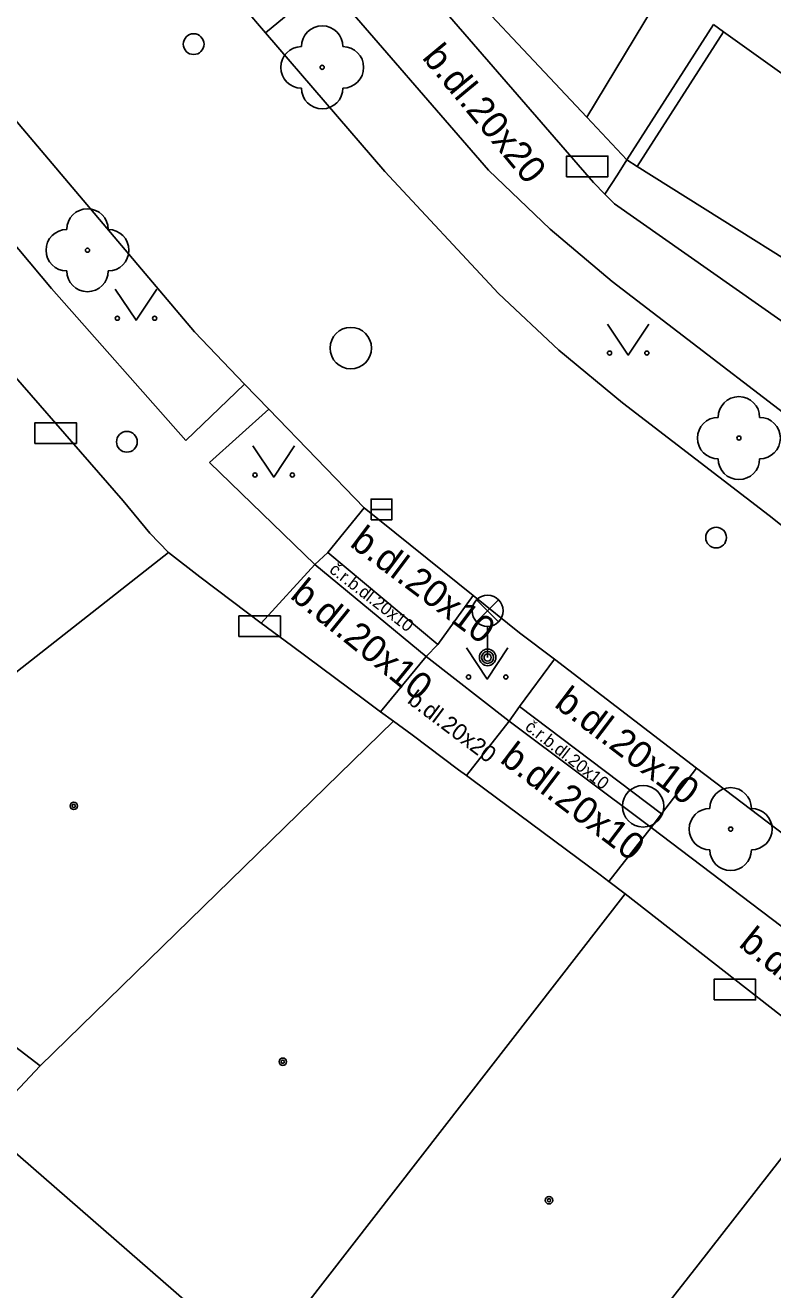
# Model space of a CAD drawing. Extents: x -595546 to -593986, y -1160845 to -1159202.
# Drawn here: x -595188.46 to -595170.44, y -1160627.43 to -1160596.94 of the extents above; entities that cross this region are included whole.
import ezdxf

# ---------------------------------------------------------------- set-up
doc = ezdxf.new("R2010")
doc.units = 0
for name, color, linetype in [('Level 22', 7, 'Continuous'), ('Level 24', 7, 'Continuous'), ('Level 27', 7, 'Continuous'), ('Level 28', 7, 'Continuous'), ('Level 33', 7, 'Continuous'), ('Level 36', 7, 'Continuous'), ('Level 39', 7, 'Continuous'), ('TM - budovy zdene_ betonove - VP', 7, 'Continuous'), ('TM - chodniky - VP', 7, 'Continuous'), ('TM - komunikace - VP', 7, 'Continuous'), ('TM - letecke snimky - pomocna linie', 7, 'Continuous'), ('TM - plot zdeny_ ohradni zed - VP', 7, 'Continuous'), ('TM - popis povrchu', 7, 'Continuous'), ('TM - rozhrani mezi zpev. plochami mezi sebou - VP', 7, 'Continuous'), ('TM - rozhrani ploch obecne - VP', 7, 'Continuous'), ('TM - vstup do budovy - zdene_ betonove', 7, 'Continuous'), ('TM - zed operna - VP', 7, 'Continuous')]:
    doc.layers.add(name, color=color, linetype=linetype)

msp = doc.modelspace()

# ---------------------------------------------------------------- linework, layer by layer
at = {"layer": 'Level 22'}
for centre in [(-595181.3, -1160597.95), (-595186.96, -1160602.36), (-595171.25, -1160606.89), (-595171.45, -1160616.32)]:
    msp.add_circle(centre, 0.05, dxfattribs=at)
for centre, start, end in [((-595181.3, -1160597.45), 0, 180), ((-595181.8, -1160597.95), 90, 270), ((-595180.8, -1160597.95), 270, 90), ((-595181.3, -1160598.45), 180, 0), ((-595186.96, -1160601.86), 0, 180), ((-595187.46, -1160602.36), 90, 270), ((-595186.46, -1160602.36), 270, 90), ((-595186.96, -1160602.86), 180, 0), ((-595171.25, -1160606.39), 0, 180), ((-595171.75, -1160606.89), 90, 270), ((-595170.75, -1160606.89), 270, 90), ((-595171.25, -1160607.39), 180, 0), ((-595171.45, -1160615.82), 0, 180), ((-595171.95, -1160616.32), 90, 270), ((-595170.95, -1160616.32), 270, 90), ((-595171.45, -1160616.82), 180, 0)]:
    msp.add_arc(centre, 0.5, start, end, dxfattribs=at)
at = {"layer": 'Level 24'}
for points in [[(-595175.408, -1160600.589), (-595174.408, -1160600.589), (-595174.408, -1160600.089), (-595175.408, -1160600.089)], [(-595188.228, -1160607.019), (-595187.228, -1160607.019), (-595187.228, -1160606.519), (-595188.228, -1160606.519)], [(-595183.308, -1160611.679), (-595182.308, -1160611.679), (-595182.308, -1160611.179), (-595183.308, -1160611.179)], [(-595171.848, -1160620.439), (-595170.848, -1160620.439), (-595170.848, -1160619.939), (-595171.848, -1160619.939)]]:
    msp.add_lwpolyline(points, close=True, dxfattribs=at)
at = {"layer": 'Level 27'}
msp.add_line((-595180.12, -1160608.61), (-595179.62, -1160608.61), dxfattribs=at)
msp.add_lwpolyline([(-595180.12, -1160608.86), (-595179.62, -1160608.86), (-595179.62, -1160608.36), (-595180.12, -1160608.36)], close=True, dxfattribs=at)
for centre in [(-595180.61, -1160604.72), (-595173.56, -1160615.77)]:
    msp.add_circle(centre, 0.5, dxfattribs=at)
at = {"layer": 'Level 28'}
for centre in [(-595184.4, -1160597.39), (-595186.01, -1160606.98), (-595171.8, -1160609.29)]:
    msp.add_circle(centre, 0.25, dxfattribs=at)
at = {"layer": 'Level 33'}
for p, q in [((-595177.575, -1160611.32), (-595177.045, -1160610.79)), ((-595177.575, -1160610.79), (-595177.045, -1160611.32)), ((-595177.31, -1160611.43), (-595177.31, -1160612.18))]:
    msp.add_line(p, q, dxfattribs=at)
for centre, radius in [((-595177.31, -1160611.055), 0.375), ((-595177.31, -1160612.18), 0.2), ((-595177.31, -1160612.18), 0.145), ((-595177.31, -1160612.18), 0.0876)]:
    msp.add_circle(centre, radius, dxfattribs=at)
at = {"layer": 'Level 36'}
for points in [[(-595186.29, -1160603.3), (-595185.79, -1160604.05), (-595185.29, -1160603.3)], [(-595174.42, -1160604.14), (-595173.92, -1160604.89), (-595173.42, -1160604.14)], [(-595182.97, -1160607.08), (-595182.47, -1160607.83), (-595181.97, -1160607.08)], [(-595177.82, -1160611.95), (-595177.32, -1160612.7), (-595176.82, -1160611.95)]]:
    msp.add_lwpolyline(points, dxfattribs=at)
for centre in [(-595186.24, -1160604), (-595185.341, -1160604), (-595174.37, -1160604.84), (-595173.471, -1160604.84), (-595182.92, -1160607.78), (-595182.021, -1160607.78), (-595177.77, -1160612.65), (-595176.871, -1160612.65)]:
    msp.add_circle(centre, 0.05, dxfattribs=at)
at = {"layer": 'Level 39'}
for centre, radius in [((-595187.29, -1160615.76), 0.09), ((-595187.29, -1160615.76), 0.0398), ((-595182.25, -1160621.93), 0.09), ((-595182.25, -1160621.93), 0.0398), ((-595175.83, -1160625.27), 0.09), ((-595175.83, -1160625.27), 0.0398)]:
    msp.add_circle(centre, radius, dxfattribs=at)
at = {"layer": 'TM - budovy zdene_ betonove - VP'}
for points in [[(-595171.62, -1160597.09), (-595171.86, -1160596.92)], [(-595167.48, -1160600.05), (-595171.62, -1160597.09)], [(-595189.73, -1160604.24), (-595186.1, -1160608.4)], [(-595185.46, -1160609.18), (-595185.01, -1160609.65)], [(-595185.01, -1160609.65), (-595194.52, -1160617.12)], [(-595185.01, -1160609.65), (-595184.25, -1160610.24)], [(-595183.46, -1160610.83), (-595182.77, -1160611.35)], [(-595182.77, -1160611.35), (-595182.04, -1160611.89)], [(-595180.28, -1160613.2), (-595179.89, -1160613.49)], [(-595179.58, -1160613.72), (-595188.1, -1160622.03)], [(-595179.89, -1160613.49), (-595179.58, -1160613.72)], [(-595179.58, -1160613.72), (-595179.13, -1160614.05)], [(-595178.01, -1160614.89), (-595177.82, -1160615.03)], [(-595177.82, -1160615.03), (-595177.66, -1160615.15)], [(-595188.1, -1160622.03), (-595194.52, -1160617.12)], [(-595174.6, -1160617.42), (-595174.39, -1160617.58)], [(-595174.39, -1160617.58), (-595173.99, -1160617.88)], [(-595182.82, -1160629.25), (-595173.99, -1160617.88)], [(-595173.99, -1160617.88), (-595169.99, -1160621.01)], [(-595188.1, -1160622.03), (-595189.46, -1160623.47)], [(-595172.23, -1160626.83), (-595168.55, -1160622.11)], [(-595182.82, -1160629.25), (-595189.46, -1160623.47)], [(-595172.23, -1160626.83), (-595177.6, -1160633.68)]]:
    msp.add_lwpolyline(points, dxfattribs=at)
at = {"layer": 'TM - chodniky - VP'}
for points in [[(-595182.67, -1160597.12), (-595181.2, -1160595.9)], [(-595181.2, -1160595.9), (-595177.29, -1160600.43)], [(-595187.83, -1160603.28), (-595192.39, -1160597.84)], [(-595177.29, -1160600.43), (-595175.8, -1160601.85)], [(-595175.8, -1160601.85), (-595174.31, -1160603.11)], [(-595174.31, -1160603.11), (-595168.35, -1160607.68)], [(-595184.59, -1160606.95), (-595187.83, -1160603.28)], [(-595183.17, -1160605.59), (-595184.59, -1160606.95)], [(-595184.02, -1160607.48), (-595182.59, -1160606.19)], [(-595181.48, -1160609.94), (-595184.02, -1160607.48)], [(-595180.29, -1160608.57), (-595181.16, -1160609.65)], [(-595181.16, -1160609.65), (-595181.48, -1160609.94)], [(-595178.51, -1160611.87), (-595177.66, -1160610.69)], [(-595178.79, -1160612.16), (-595178.51, -1160611.87)], [(-595176.79, -1160613.72), (-595178.79, -1160612.16)], [(-595175.7, -1160612.22), (-595176.54, -1160613.36)], [(-595176.54, -1160613.36), (-595176.79, -1160613.72)], [(-595173.12, -1160615.95), (-595172.27, -1160614.85)], [(-595173.37, -1160616.28), (-595173.12, -1160615.95)], [(-595168.78, -1160619.76), (-595173.37, -1160616.28)]]:
    msp.add_lwpolyline(points, dxfattribs=at)
at = {"layer": 'TM - komunikace - VP'}
for points in [[(-595190.95, -1160596.57), (-595184.38, -1160604.33)], [(-595182.67, -1160597.12), (-595183.19, -1160596.51)], [(-595179.79, -1160600.46), (-595182.67, -1160597.12)], [(-595177.05, -1160603.4), (-595179.79, -1160600.46)], [(-595175.59, -1160604.77), (-595177.05, -1160603.4)], [(-595183.17, -1160605.59), (-595184.38, -1160604.33)], [(-595174.06, -1160606.04), (-595175.59, -1160604.77)], [(-595182.59, -1160606.19), (-595183.17, -1160605.59)], [(-595170.52, -1160608.76), (-595174.06, -1160606.04)], [(-595180.29, -1160608.57), (-595182.59, -1160606.19)], [(-595177.66, -1160610.69), (-595180.29, -1160608.57)], [(-595169.7, -1160609.41), (-595170.52, -1160608.76)], [(-595176.54, -1160611.59), (-595177.66, -1160610.69)], [(-595175.7, -1160612.22), (-595176.54, -1160611.59)], [(-595172.27, -1160614.85), (-595175.7, -1160612.22)], [(-595171.37, -1160615.53), (-595172.27, -1160614.85)], [(-595167.69, -1160618.33), (-595171.37, -1160615.53)]]:
    msp.add_lwpolyline(points, dxfattribs=at)
at = {"layer": 'TM - letecke snimky - pomocna linie'}
msp.add_lwpolyline([(-595175.84, -1160593.45), (-595173.31, -1160596.49), (-595174.92, -1160599.15)], dxfattribs=at)
at = {"layer": 'TM - plot zdeny_ ohradni zed - VP'}
for points in [[(-595174.76, -1160600.73), (-595174.48, -1160601.01)], [(-595174.48, -1160601.01), (-595174.25, -1160601.24)]]:
    msp.add_lwpolyline(points, dxfattribs=at)
at = {"layer": 'TM - rozhrani mezi zpev. plochami mezi sebou - VP'}
for points in [[(-595178.51, -1160611.87), (-595181.16, -1160609.65)], [(-595182.77, -1160611.35), (-595181.48, -1160609.94)], [(-595178.79, -1160612.16), (-595181.48, -1160609.94)], [(-595179.89, -1160613.49), (-595178.79, -1160612.16)], [(-595173.12, -1160615.95), (-595176.54, -1160613.36)], [(-595176.79, -1160613.72), (-595177.82, -1160615.03)], [(-595173.37, -1160616.28), (-595176.79, -1160613.72)], [(-595174.39, -1160617.58), (-595173.37, -1160616.28)]]:
    msp.add_lwpolyline(points, dxfattribs=at)
at = {"layer": 'TM - rozhrani ploch obecne - VP'}
for points in [[(-595174.92, -1160599.15), (-595178.88, -1160594.93)], [(-595173.95, -1160600.18), (-595171.86, -1160596.92)], [(-595171.62, -1160597.09), (-595173.7, -1160600.34)], [(-595173.95, -1160600.18), (-595174.92, -1160599.15)], [(-595174.48, -1160601.01), (-595174.18, -1160600.54), (-595173.95, -1160600.18)], [(-595173.95, -1160600.18), (-595173.7, -1160600.34)], [(-595173.7, -1160600.34), (-595167.68, -1160604.12)]]:
    msp.add_lwpolyline(points, dxfattribs=at)
at = {"layer": 'TM - vstup do budovy - zdene_ betonove'}
for points in [[(-595185.46, -1160609.18), (-595186.1, -1160608.4)], [(-595183.46, -1160610.83), (-595184.25, -1160610.24)], [(-595180.28, -1160613.2), (-595182.04, -1160611.89)], [(-595178.01, -1160614.89), (-595179.13, -1160614.05)], [(-595174.6, -1160617.42), (-595177.66, -1160615.15)]]:
    msp.add_lwpolyline(points, dxfattribs=at)
at = {"layer": 'TM - zed operna - VP'}
for points in [[(-595179.39, -1160595.38), (-595174.76, -1160600.73)], [(-595174.25, -1160601.24), (-595168.46, -1160605.3)]]:
    msp.add_lwpolyline(points, dxfattribs=at)

# ---------------------------------------------------------------- texts
at = {"layer": 'TM - popis povrchu'}
for s, height, rotation, p in [('b.dl.20x20', 0.65, 309.6946, (-595178.91, -1160597.72)), ('b.dl.20x10', 0.65, 323.1723, (-595180.66, -1160609.48)), ('č.r.b.dl.20x10', 0.3, 322.3048, (-595181.15, -1160610.11)), ('b.dl.20x10', 0.65, 320.957, (-595182.1, -1160610.73)), ('b.dl.20x10', 0.65, 322.8661, (-595175.73, -1160613.35)), ('b.dl.20x20', 0.4, 323, (-595179.27, -1160613.26)), ('č.r.b.dl.20x10', 0.3, 321.9639, (-595176.43, -1160613.9)), ('b.dl.20x10', 0.65, 322.7767, (-595177.04, -1160614.69)), ('b.dl.20x20', 0.65, 321.1457, (-595171.28, -1160619.13))]:
    msp.add_text(s, height=height, rotation=rotation, dxfattribs=at).set_placement(p)

doc.saveas('drawing.dxf')
